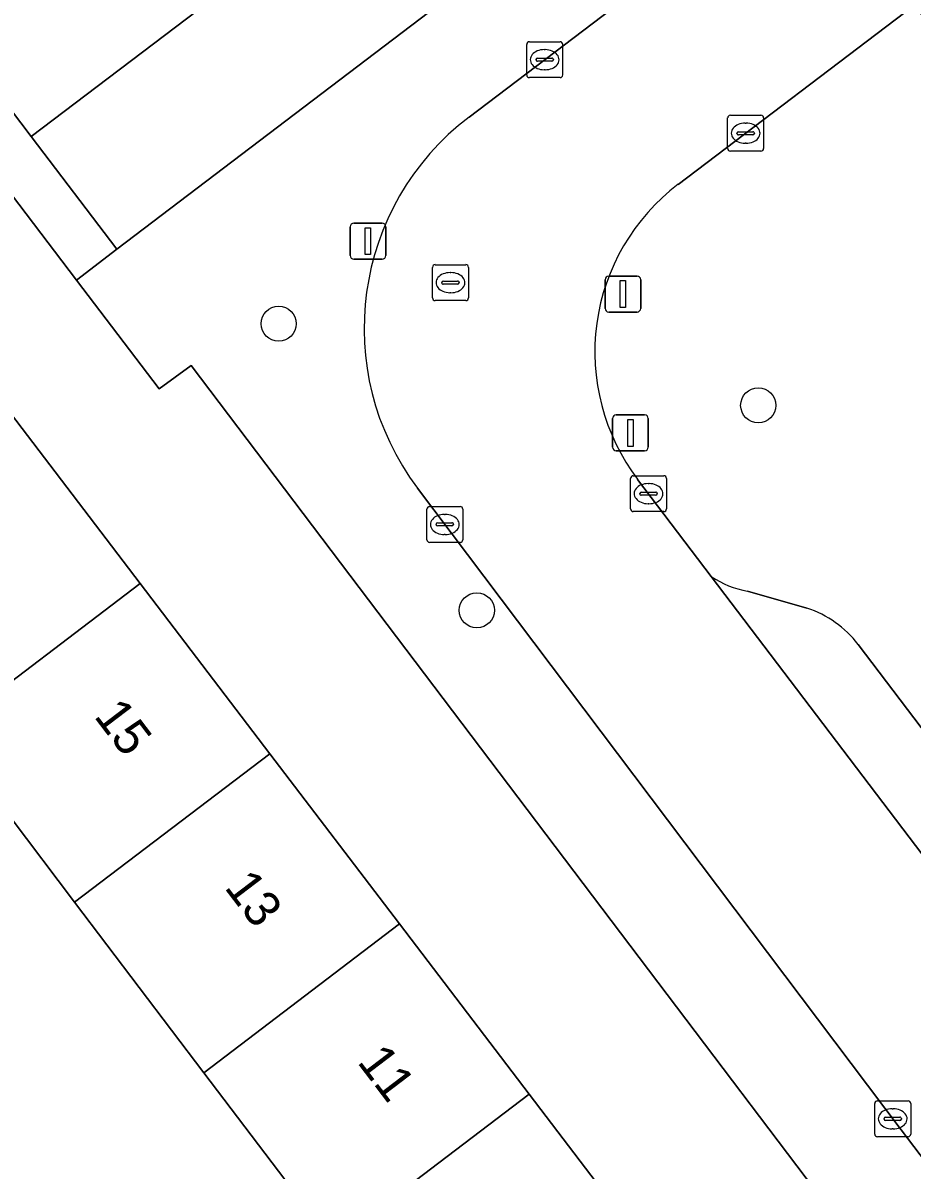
# Model space of a CAD drawing. Extents: x 160030 to 160839, y 385325 to 386450.
# Drawn here: x 160297.9 to 160322.65, y 385818.69 to 385850.63 of the extents above; entities that cross this region are included whole.
import ezdxf

# ---------------------------------------------------------------- set-up
doc = ezdxf.new("R2010")
doc.units = 0
for name, color, linetype in [('IMGEO_Afsluitpaal', 7, 'Continuous'), ('IMGEO_Boom', 7, 'Continuous'), ('IMGEO_Erf', 7, 'Continuous'), ('IMGEO_Groenvoorziening', 7, 'Continuous'), ('IMGEO_Kolk', 7, 'Continuous'), ('IMGEO_Lichtmast', 7, 'Continuous'), ('IMGEO_Pand', 7, 'Continuous'), ('IMGEO_Pand_nummerreeks', 7, 'Continuous'), ('IMGEO_Parkeervlak_open', 7, 'Continuous'), ('IMGEO_Rijbaan_lokaal_open', 7, 'Continuous'), ('IMGEO_Rioolput', 7, 'Continuous'), ('IMGEO_Voetpad_open', 7, 'Continuous')]:
    doc.layers.add(name, color=color, linetype=linetype)

msp = doc.modelspace()

# ---------------------------------------------------------------- linework, layer by layer
at = {"layer": 'IMGEO_Afsluitpaal'}
for p, q in [((160314.204, 385843.581), (160314.994, 385843.581)), ((160314.994, 385843.581), (160314.204, 385843.581)), ((160314.104, 385842.681), (160314.104, 385843.481)), ((160314.104, 385843.481), (160314.104, 385842.681)), ((160315.094, 385843.481), (160315.094, 385842.681)), ((160315.094, 385842.681), (160315.094, 385843.481)), ((160314.994, 385842.581), (160314.204, 385842.581)), ((160314.204, 385842.581), (160314.994, 385842.581)), ((160314.413, 385839.716), (160315.203, 385839.716)), ((160315.203, 385839.716), (160314.413, 385839.716)), ((160314.313, 385838.816), (160314.313, 385839.616)), ((160314.313, 385839.616), (160314.313, 385838.816)), ((160315.303, 385839.616), (160315.303, 385838.816)), ((160315.303, 385838.816), (160315.303, 385839.616)), ((160315.203, 385838.716), (160314.413, 385838.716)), ((160314.413, 385838.716), (160315.203, 385838.716))]:
    msp.add_line(p, q, dxfattribs=at)
for points in [[(160314.524, 385843.456), (160314.674, 385843.456), (160314.674, 385842.706), (160314.524, 385842.706), (160314.524, 385843.456)], [(160314.733, 385839.591), (160314.883, 385839.591), (160314.883, 385838.841), (160314.733, 385838.841), (160314.733, 385839.591)]]:
    msp.add_lwpolyline(points, dxfattribs=at)
for centre, start, end in [((160314.204, 385843.481), 90, 180), ((160314.204, 385843.481), 90, 180), ((160314.994, 385843.481), 0, 90), ((160314.994, 385843.481), 360, 90), ((160314.204, 385842.681), 180, 270), ((160314.204, 385842.681), 180, 270), ((160314.994, 385842.681), 270, 0), ((160314.994, 385842.681), 270, 0), ((160314.413, 385839.616), 90, 180), ((160314.413, 385839.616), 90, 180), ((160315.203, 385839.616), 0, 90), ((160315.203, 385839.616), 360, 90), ((160314.413, 385838.816), 180, 270), ((160314.413, 385838.816), 180, 270), ((160315.203, 385838.816), 270, 0), ((160315.203, 385838.816), 270, 0)]:
    msp.add_arc(centre, 0.1, start, end, dxfattribs=at)
at = {"layer": 'IMGEO_Boom'}
for centre in [(160305.02, 385842.255), (160318.365, 385839.983), (160310.533, 385834.277)]:
    msp.add_circle(centre, 0.489, dxfattribs=at)
at = {"layer": 'IMGEO_Erf'}
for points in [[(160356.339, 385890.539), (160355.831, 385891.162), (160350.897, 385887.426), (160346.114, 385883.805), (160341.33, 385880.183), (160336.547, 385876.561), (160331.763, 385872.939), (160326.98, 385869.318), (160322.196, 385865.696), (160317.412, 385862.073), (160312.629, 385858.452), (160307.845, 385854.83), (160303.062, 385851.208), (160298.129, 385847.473), (160300.518, 385844.329), (160355.835, 385886.372)], [(160302.585, 385841.09), (160301.695, 385840.441), (160299.39, 385843.472), (160296.787, 385846.896), (160293.838, 385844.652), (160297.555, 385839.767), (160301.163, 385835.026), (160304.771, 385830.284), (160308.379, 385825.543), (160311.987, 385820.801), (160315.595, 385816.06), (160319.203, 385811.318), (160322.811, 385806.577), (160326.419, 385801.836), (160330.134, 385796.954), (160325.136, 385793.154)], [(160333.469, 385800.262), (160302.585, 385841.09)], [(160306.531, 385816.65), (160302.935, 385821.4), (160299.338, 385826.151), (160295.742, 385830.901), (160292.145, 385835.651), (160288.43, 385840.558), (160280.539, 385834.575), (160283.637, 385830.585), (160281.5, 385828.925), (160282.831, 385827.212), (160284.541, 385828.507), (160287.487, 385824.671), (160290.373, 385820.913), (160288.481, 385819.459), (160289.842, 385817.685), (160292.178, 385819.479), (160295.203, 385815.538)]]:
    msp.add_lwpolyline(points, dxfattribs=at)
at = {"layer": 'IMGEO_Groenvoorziening'}
for points in [[(160321.143, 385833.325), (160328.543, 385823.58), (160338.075, 385830.835), (160322.717, 385851.129), (160316.136, 385846.137)], [(160315.009, 385837.923), (160317.059, 385835.221)], [(160318.067, 385834.807), (160319.72, 385834.334)]]:
    msp.add_lwpolyline(points, dxfattribs=at)
for centre, radius, start, end in [((160319.679, 385841.467), 5.862, 127.1812, 217.1938), ((160318.535, 385837.38), 2.615, 235.6468, 259.6959), ((160318.848, 385831.596), 2.874, 36.9942, 72.3275)]:
    msp.add_arc(centre, radius, start, end, dxfattribs=at)
at = {"layer": 'IMGEO_Kolk'}
for p, q in [((160311.921, 385849.182), (160311.921, 385850.034)), ((160311.996, 385850.108), (160312.848, 385850.108)), ((160312.922, 385850.034), (160312.922, 385849.182)), ((160312.18, 385849.602), (160312.18, 385849.614)), ((160312.223, 385849.651), (160312.621, 385849.651)), ((160312.409, 385849.888), (160312.434, 385849.888)), ((160312.664, 385849.614), (160312.664, 385849.602)), ((160312.618, 385849.565), (160312.22, 385849.565)), ((160312.432, 385849.328), (160312.407, 385849.328)), ((160312.848, 385849.108), (160311.996, 385849.108)), ((160317.589, 385848.06), (160318.441, 385848.06)), ((160317.514, 385847.134), (160317.514, 385847.986)), ((160318.002, 385847.84), (160318.027, 385847.84)), ((160318.515, 385847.986), (160318.515, 385847.134)), ((160317.773, 385847.554), (160317.773, 385847.566)), ((160318.211, 385847.517), (160317.813, 385847.517)), ((160317.816, 385847.603), (160318.214, 385847.603)), ((160318.257, 385847.566), (160318.257, 385847.554)), ((160318.441, 385847.06), (160317.589, 385847.06)), ((160318.025, 385847.28), (160318, 385847.28)), ((160314.812, 385837.098), (160314.812, 385837.95)), ((160314.887, 385838.024), (160315.739, 385838.024)), ((160315.3, 385837.804), (160315.325, 385837.804)), ((160315.813, 385837.95), (160315.813, 385837.098)), ((160315.071, 385837.518), (160315.071, 385837.53)), ((160315.509, 385837.481), (160315.111, 385837.481)), ((160315.114, 385837.567), (160315.512, 385837.567)), ((160315.555, 385837.53), (160315.555, 385837.518)), ((160309.217, 385837.167), (160310.069, 385837.167)), ((160315.323, 385837.244), (160315.298, 385837.244)), ((160309.142, 385836.241), (160309.142, 385837.093)), ((160309.63, 385836.947), (160309.655, 385836.947)), ((160310.143, 385837.093), (160310.143, 385836.241)), ((160315.739, 385837.024), (160314.887, 385837.024)), ((160309.401, 385836.661), (160309.401, 385836.673)), ((160309.839, 385836.624), (160309.441, 385836.624)), ((160309.444, 385836.71), (160309.842, 385836.71)), ((160309.885, 385836.673), (160309.885, 385836.661)), ((160309.653, 385836.387), (160309.628, 385836.387)), ((160310.069, 385836.167), (160309.217, 385836.167)), ((160321.607, 385819.691), (160321.607, 385820.543)), ((160321.682, 385820.617), (160322.534, 385820.617)), ((160322.608, 385820.543), (160322.608, 385819.691)), ((160322.095, 385820.397), (160322.12, 385820.397)), ((160321.866, 385820.111), (160321.866, 385820.123)), ((160322.304, 385820.074), (160321.906, 385820.074)), ((160321.909, 385820.16), (160322.307, 385820.16)), ((160322.35, 385820.123), (160322.35, 385820.111)), ((160322.534, 385819.617), (160321.682, 385819.617)), ((160322.118, 385819.837), (160322.093, 385819.837))]:
    msp.add_line(p, q, dxfattribs=at)
for points in [[(160311.921, 385849.182), (160311.921, 385850.034)], [(160311.996, 385850.108), (160312.848, 385850.108)], [(160312.922, 385850.034), (160312.922, 385849.182)], [(160312.848, 385849.108), (160311.996, 385849.108)], [(160317.589, 385848.06), (160318.441, 385848.06)], [(160317.514, 385847.134), (160317.514, 385847.986)], [(160318.515, 385847.986), (160318.515, 385847.134)], [(160318.441, 385847.06), (160317.589, 385847.06)], [(160314.812, 385837.098), (160314.812, 385837.95)], [(160314.887, 385838.024), (160315.739, 385838.024)], [(160315.813, 385837.95), (160315.813, 385837.098)], [(160309.217, 385837.167), (160310.069, 385837.167)], [(160309.142, 385836.241), (160309.142, 385837.093)], [(160310.143, 385837.093), (160310.143, 385836.241)], [(160315.739, 385837.024), (160314.887, 385837.024)], [(160310.069, 385836.167), (160309.217, 385836.167)], [(160321.607, 385819.691), (160321.607, 385820.543)], [(160321.682, 385820.617), (160322.534, 385820.617)], [(160322.608, 385820.543), (160322.608, 385819.691)], [(160322.534, 385819.617), (160321.682, 385819.617)]]:
    msp.add_lwpolyline(points, dxfattribs=at)
for centre, radius, start, end in [((160311.998, 385850.032), 0.0765, 91.552, 178.448), ((160311.998, 385850.032), 0.0765, 91.552, 178.448), ((160312.846, 385850.032), 0.0765, 1.552, 88.448), ((160312.846, 385850.032), 0.0765, 1.552, 88.448), ((160312.22, 385849.611), 0.0403, 85.8775, 175.7526), ((160312.217, 385849.601), 0.0366, 178.938, 274.7102), ((160312.621, 385849.608), 0.043, 264.8664, 352.4533), ((160312.625, 385849.613), 0.0386, 1.7309, 96.639), ((160311.998, 385849.184), 0.0765, 181.552, 268.448), ((160311.998, 385849.184), 0.0765, 181.552, 268.448), ((160312.846, 385849.184), 0.0765, 271.552, 358.448), ((160312.846, 385849.184), 0.0765, 271.552, 358.448), ((160317.591, 385847.984), 0.0765, 91.552, 178.448), ((160317.591, 385847.984), 0.0765, 91.552, 178.448), ((160318.439, 385847.984), 0.0765, 1.552, 88.448), ((160318.439, 385847.984), 0.0765, 1.552, 88.448), ((160317.813, 385847.563), 0.0403, 85.8775, 175.7526), ((160317.81, 385847.553), 0.0366, 178.938, 274.7102), ((160318.214, 385847.56), 0.043, 264.8664, 352.4533), ((160318.218, 385847.565), 0.0386, 1.7309, 96.639), ((160317.591, 385847.136), 0.0765, 181.552, 268.448), ((160317.591, 385847.136), 0.0765, 181.552, 268.448), ((160318.439, 385847.136), 0.0765, 271.552, 358.448), ((160318.439, 385847.136), 0.0765, 271.552, 358.448), ((160314.889, 385837.948), 0.0765, 91.552, 178.448), ((160314.889, 385837.948), 0.0765, 91.552, 178.448), ((160315.737, 385837.948), 0.0765, 1.552, 88.448), ((160315.737, 385837.948), 0.0765, 1.552, 88.448), ((160315.111, 385837.527), 0.0403, 85.8775, 175.7526), ((160315.108, 385837.517), 0.0366, 178.938, 274.7102), ((160315.512, 385837.524), 0.043, 264.8664, 352.4533), ((160315.516, 385837.529), 0.0386, 1.7309, 96.639), ((160309.219, 385837.091), 0.0765, 91.552, 178.448), ((160309.219, 385837.091), 0.0765, 91.552, 178.448), ((160310.067, 385837.091), 0.0765, 1.552, 88.448), ((160310.067, 385837.091), 0.0765, 1.552, 88.448), ((160314.889, 385837.1), 0.0765, 181.552, 268.448), ((160314.889, 385837.1), 0.0765, 181.552, 268.448), ((160315.737, 385837.1), 0.0765, 271.552, 358.448), ((160315.737, 385837.1), 0.0765, 271.552, 358.448), ((160309.441, 385836.67), 0.0403, 85.8775, 175.7526), ((160309.438, 385836.66), 0.0366, 178.938, 274.7102), ((160309.842, 385836.667), 0.043, 264.8664, 352.4533), ((160309.846, 385836.672), 0.0386, 1.7309, 96.639), ((160309.219, 385836.243), 0.0765, 181.552, 268.448), ((160309.219, 385836.243), 0.0765, 181.552, 268.448), ((160310.067, 385836.243), 0.0765, 271.552, 358.448), ((160310.067, 385836.243), 0.0765, 271.552, 358.448), ((160321.684, 385820.541), 0.0765, 91.552, 178.448), ((160321.684, 385820.541), 0.0765, 91.552, 178.448), ((160322.532, 385820.541), 0.0765, 1.552, 88.448), ((160322.532, 385820.541), 0.0765, 1.552, 88.448), ((160321.906, 385820.12), 0.0403, 85.8775, 175.7526), ((160321.903, 385820.11), 0.0366, 178.938, 274.7102), ((160322.307, 385820.117), 0.043, 264.8664, 352.4533), ((160322.311, 385820.122), 0.0386, 1.7309, 96.639), ((160321.684, 385819.693), 0.0765, 181.552, 268.448), ((160321.684, 385819.693), 0.0765, 181.552, 268.448), ((160322.532, 385819.693), 0.0765, 271.552, 358.448), ((160322.532, 385819.693), 0.0765, 271.552, 358.448)]:
    msp.add_arc(centre, radius, start, end, dxfattribs=at)
for centre, major_axis, ratio, start_param, end_param in [((160312.408, 385849.608), (-0.387, 0.002), 0.722429, 4.712389, 7.853982), ((160312.433, 385849.608), (-0.39, 0.002), 0.717154, 1.570796, 4.712389), ((160318.001, 385847.56), (-0.387, 0.002), 0.722429, 4.712389, 7.853982), ((160318.026, 385847.56), (-0.39, 0.002), 0.717154, 1.570796, 4.712389), ((160315.299, 385837.524), (-0.387, 0.002), 0.722429, 4.712389, 7.853982), ((160315.324, 385837.524), (-0.39, 0.002), 0.717154, 1.570796, 4.712389), ((160309.629, 385836.667), (-0.387, 0.002), 0.722429, 4.712389, 7.853982), ((160309.654, 385836.667), (-0.39, 0.002), 0.717154, 1.570796, 4.712389), ((160322.094, 385820.117), (-0.387, 0.002), 0.722429, 4.712389, 7.853982), ((160322.119, 385820.117), (-0.39, 0.002), 0.717154, 1.570796, 4.712389)]:
    msp.add_ellipse(centre, major_axis=major_axis, ratio=ratio, start_param=start_param, end_param=end_param, dxfattribs=at)
at = {"layer": 'IMGEO_Lichtmast'}
for p, q in [((160307.008, 385844.155), (160307.008, 385844.955)), ((160307.008, 385844.955), (160307.008, 385844.155)), ((160307.108, 385845.055), (160307.898, 385845.055)), ((160307.898, 385845.055), (160307.108, 385845.055)), ((160307.998, 385844.955), (160307.998, 385844.155)), ((160307.998, 385844.155), (160307.998, 385844.955)), ((160307.898, 385844.055), (160307.108, 385844.055)), ((160307.108, 385844.055), (160307.898, 385844.055))]:
    msp.add_line(p, q, dxfattribs=at)
msp.add_lwpolyline([(160307.428, 385844.93), (160307.578, 385844.93), (160307.578, 385844.18), (160307.428, 385844.18), (160307.428, 385844.93)], dxfattribs=at)
for centre, start, end in [((160307.108, 385844.955), 90, 180), ((160307.108, 385844.955), 90, 180), ((160307.898, 385844.955), 0, 90), ((160307.898, 385844.955), 360, 90), ((160307.108, 385844.155), 180, 270), ((160307.108, 385844.155), 180, 270), ((160307.898, 385844.155), 270, 0), ((160307.898, 385844.155), 270, 0)]:
    msp.add_arc(centre, 0.1, start, end, dxfattribs=at)
at = {"layer": 'IMGEO_Pand'}
for points in [[(160294.063, 385852.843), (160298.129, 385847.473), (160303.062, 385851.208), (160298.997, 385856.578)], [(160292.145, 385835.651), (160295.742, 385830.901), (160301.163, 385835.026), (160297.555, 385839.767)], [(160304.771, 385830.284), (160301.163, 385835.026), (160295.742, 385830.901), (160299.338, 385826.151)], [(160308.379, 385825.543), (160304.771, 385830.284), (160299.338, 385826.151), (160302.935, 385821.4)], [(160302.935, 385821.4), (160306.531, 385816.65), (160311.987, 385820.801), (160308.379, 385825.543)], [(160306.531, 385816.65), (160310.127, 385811.9), (160315.595, 385816.06), (160311.987, 385820.801)]]:
    msp.add_lwpolyline(points, close=True, dxfattribs=at)
at = {"layer": 'IMGEO_Parkeervlak_open'}
for points in [[(160317.059, 385835.221), (160339.626, 385805.488)], [(160319.72, 385834.334), (160318.067, 385834.807)], [(160329.027, 385822.942), (160328.543, 385823.58), (160321.143, 385833.325)]]:
    msp.add_lwpolyline(points, dxfattribs=at)
for centre, radius, start, end in [((160318.535, 385837.38), 2.615, 235.6468, 259.6959), ((160318.848, 385831.596), 2.874, 36.9942, 72.3275)]:
    msp.add_arc(centre, radius, start, end, dxfattribs=at)
at = {"layer": 'IMGEO_Rijbaan_lokaal_open'}
for points in [[(160357.581, 385883.992), (160334.468, 385866.348), (160310.316, 385848.008)], [(160316.136, 385846.137), (160322.717, 385851.129), (160326.328, 385853.868), (160336.283, 385861.419), (160353.387, 385874.369), (160360.393, 385880.034)], [(160341.22, 385803.374), (160341.021, 385803.649), (160339.626, 385805.488), (160317.059, 385835.221), (160315.009, 385837.923)], [(160308.883, 385837.678), (160322.339, 385819.813), (160334.964, 385803.193)]]:
    msp.add_lwpolyline(points, dxfattribs=at)
for centre, radius, start, end in [((160314.785, 385842.124), 7.389, 127.2141, 216.9903), ((160319.679, 385841.467), 5.862, 127.1812, 217.1938)]:
    msp.add_arc(centre, radius, start, end, dxfattribs=at)
at = {"layer": 'IMGEO_Rioolput'}
for p, q in [((160309.374, 385843.9), (160310.226, 385843.9)), ((160309.299, 385842.974), (160309.299, 385843.826)), ((160309.787, 385843.68), (160309.812, 385843.68)), ((160310.3, 385843.826), (160310.3, 385842.974)), ((160309.558, 385843.394), (160309.558, 385843.406)), ((160309.996, 385843.357), (160309.598, 385843.357)), ((160309.601, 385843.443), (160309.999, 385843.443)), ((160310.042, 385843.406), (160310.042, 385843.394)), ((160310.226, 385842.9), (160309.374, 385842.9)), ((160309.81, 385843.12), (160309.785, 385843.12))]:
    msp.add_line(p, q, dxfattribs=at)
for points in [[(160309.374, 385843.9), (160310.226, 385843.9)], [(160309.299, 385842.974), (160309.299, 385843.826)], [(160310.3, 385843.826), (160310.3, 385842.974)], [(160310.226, 385842.9), (160309.374, 385842.9)]]:
    msp.add_lwpolyline(points, dxfattribs=at)
for centre, radius, start, end in [((160309.376, 385843.824), 0.0765, 91.552, 178.448), ((160309.376, 385843.824), 0.0765, 91.552, 178.448), ((160310.224, 385843.824), 0.0765, 1.552, 88.448), ((160310.224, 385843.824), 0.0765, 1.552, 88.448), ((160309.598, 385843.403), 0.0403, 85.8775, 175.7526), ((160309.595, 385843.393), 0.0366, 178.938, 274.7102), ((160309.999, 385843.4), 0.043, 264.8664, 352.4533), ((160310.003, 385843.405), 0.0386, 1.7309, 96.639), ((160309.376, 385842.976), 0.0765, 181.552, 268.448), ((160309.376, 385842.976), 0.0765, 181.552, 268.448), ((160310.224, 385842.976), 0.0765, 271.552, 358.448), ((160310.224, 385842.976), 0.0765, 271.552, 358.448)]:
    msp.add_arc(centre, radius, start, end, dxfattribs=at)
for centre, major_axis, ratio, start_param, end_param in [((160309.786, 385843.4), (-0.387, 0.002), 0.722429, 4.712389, 7.853982), ((160309.811, 385843.4), (-0.39, 0.002), 0.717154, 1.570796, 4.712389)]:
    msp.add_ellipse(centre, major_axis=major_axis, ratio=ratio, start_param=start_param, end_param=end_param, dxfattribs=at)
at = {"layer": 'IMGEO_Voetpad_open'}
for points in [[(160355.835, 385886.372), (160300.518, 385844.329), (160299.39, 385843.472), (160301.695, 385840.441), (160302.585, 385841.09), (160333.469, 385800.262)], [(160310.316, 385848.008), (160334.468, 385866.348), (160357.581, 385883.992)], [(160296.787, 385846.896), (160299.39, 385843.472), (160300.518, 385844.329), (160298.129, 385847.473), (160294.063, 385852.843)], [(160334.964, 385803.193), (160322.339, 385819.813), (160308.883, 385837.678)]]:
    msp.add_lwpolyline(points, dxfattribs=at)
msp.add_arc((160314.785, 385842.124), 7.389, 127.2141, 216.9903, dxfattribs=at)

# ---------------------------------------------------------------- texts
at = {"layer": 'IMGEO_Pand_nummerreeks'}
for s, p in [('15', (160299.856, 385831.326)), ('13', (160303.486, 385826.557)), ('11', (160307.184, 385821.696))]:
    msp.add_text(s, height=1, rotation=307.2695, dxfattribs=at).set_placement(p)

doc.saveas('drawing.dxf')
